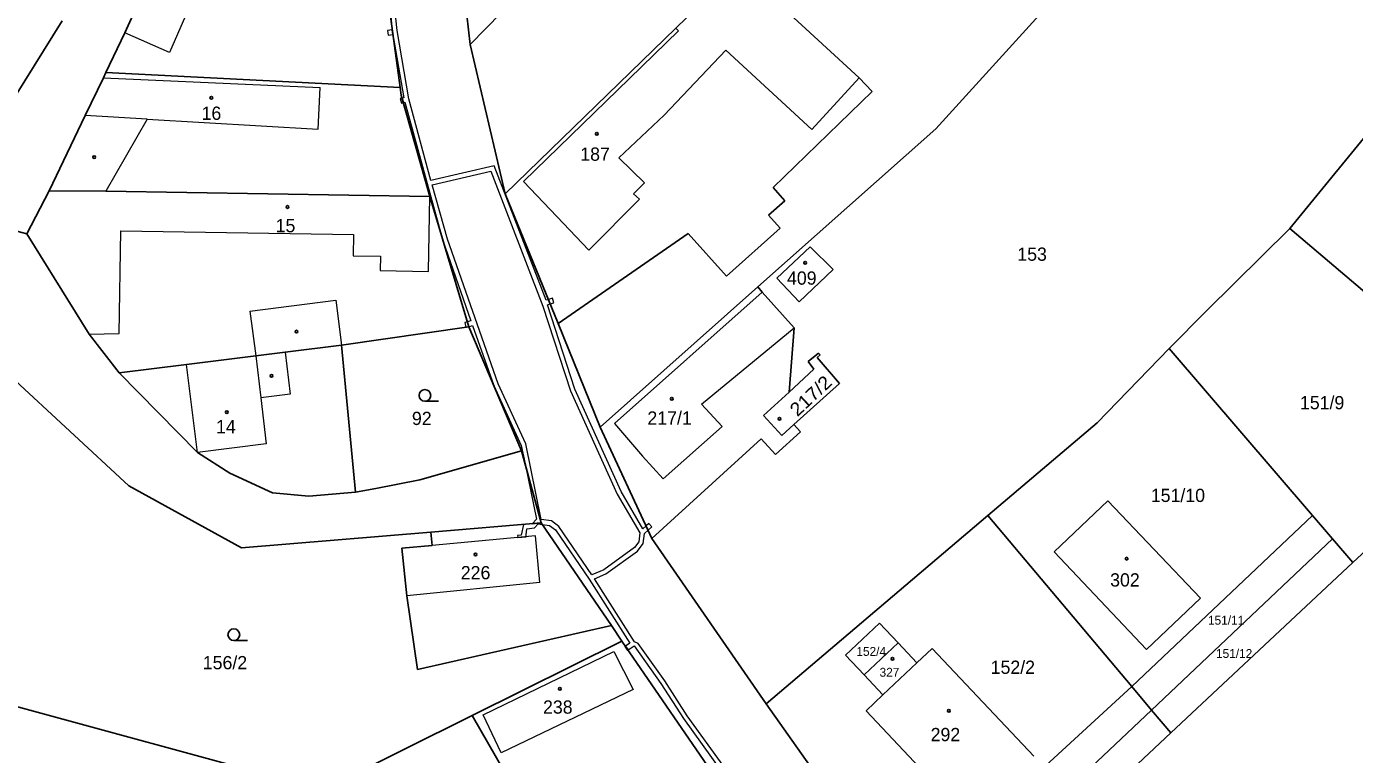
# Model space of a CAD drawing. Extents: x -694609 to -690140, y -1033292 to -1029794.
# Drawn here: x -693128 to -692957.6, y -1031416.8 to -1031323.3 of the extents above; entities that cross this region are included whole.
import ezdxf
from ezdxf.enums import TextEntityAlignment as Align

# ---------------------------------------------------------------- set-up
doc = ezdxf.new("R2010")
doc.units = 0
doc.header["$LTSCALE"] = 0.68
for name, color, linetype, lineweight in [('1', 7, 'Continuous', 25), ('13', 7, 'Continuous', 13), ('3', 7, 'Continuous', 25), ('4', 7, 'Continuous', 13), ('5', 7, 'Continuous', 25)]:
    doc.layers.add(name, color=color, linetype=linetype, lineweight=lineweight)
doc.layers.add('2', color=7, linetype='Continuous')

msp = doc.modelspace()

# ---------------------------------------------------------------- linework, layer by layer
at = {"layer": '1'}
for p, q in [((-693011.32, -1031336.45), (-692982.62, -1031304.77)), ((-693071.07, -1031325.64), (-693054.38, -1031308.42)), ((-693109.53, -1031311.17), (-693115.38, -1031324.14)), ((-693044.7, -1031323.52), (-693036.63, -1031315.66)), ((-693081.81, -1031318.46), (-693080.06, -1031331.16)), ((-693071.72, -1031320), (-693071.07, -1031325.64)), ((-693032.19, -1031319.75), (-693021.16, -1031329.91)), ((-693123.43, -1031322.59), (-693138.69, -1031347.09)), ((-693066.58, -1031344.79), (-693044.7, -1031323.52)), ((-693115.38, -1031324.14), (-693117.81, -1031329.22)), ((-693071.07, -1031325.64), (-693066.58, -1031344.79)), ((-693118.14, -1031329.9), (-693120.46, -1031334.74)), ((-693117.81, -1031329.22), (-693118.14, -1031329.9)), ((-693117.81, -1031329.22), (-693080.06, -1031331.16)), ((-693021.16, -1031329.91), (-693019.51, -1031331.67)), ((-693080.06, -1031331.16), (-693079.92, -1031332.14)), ((-693079.92, -1031332.14), (-693076.25, -1031345.16)), ((-693032.23, -1031344.01), (-693019.51, -1031331.67)), ((-693120.46, -1031334.74), (-693125.1, -1031344.42)), ((-692965.91, -1031349.24), (-692953.66, -1031334.24)), ((-693011.32, -1031336.45), (-693034.18, -1031356.76)), ((-693032.23, -1031344.01), (-693030.7, -1031345.69)), ((-693125.1, -1031344.42), (-693127.97, -1031349.93)), ((-693117.81, -1031344.47), (-693125.1, -1031344.42)), ((-693076.25, -1031345.16), (-693117.81, -1031344.47)), ((-693076.25, -1031345.16), (-693071.27, -1031361.86)), ((-693059.81, -1031361.44), (-693066.58, -1031344.79)), ((-693030.7, -1031345.69), (-693032.8, -1031347.55)), ((-693127.97, -1031349.93), (-693138.69, -1031347.09)), ((-693032.8, -1031347.55), (-693031.3, -1031349.23)), ((-693031.3, -1031349.23), (-693038.21, -1031355.38)), ((-692965.91, -1031349.24), (-692976.61, -1031359.82)), ((-692937.71, -1031373.28), (-692965.91, -1031349.24)), ((-693127.97, -1031349.93), (-693119.97, -1031362.82)), ((-693043.1, -1031349.89), (-693059.81, -1031361.44)), ((-693038.21, -1031355.38), (-693043.1, -1031349.89)), ((-693031.76, -1031355.61), (-693027.47, -1031351.59)), ((-693027.47, -1031351.59), (-693024.52, -1031354.53)), ((-693024.52, -1031354.53), (-693028.87, -1031358.66)), ((-693028.87, -1031358.66), (-693031.76, -1031355.61)), ((-693034.18, -1031356.76), (-693054.4, -1031374.74)), ((-693033.63, -1031357.42), (-693034.18, -1031356.76)), ((-693029.51, -1031362.02), (-693033.63, -1031357.42)), ((-692976.61, -1031359.82), (-692981.39, -1031364.66)), ((-693119.97, -1031362.82), (-693116.13, -1031367.79)), ((-693071.27, -1031361.86), (-693087.61, -1031364.21)), ((-693071.27, -1031361.86), (-693064.5, -1031377.79)), ((-693054.4, -1031374.74), (-693059.81, -1031361.44)), ((-693029.51, -1031362.02), (-693030.17, -1031370.26)), ((-693094.83, -1031365.12), (-693087.61, -1031364.21)), ((-693087.61, -1031364.21), (-693085.81, -1031383.1)), ((-692981.39, -1031364.66), (-692990.66, -1031374.2)), ((-692963.02, -1031386.08), (-692981.39, -1031364.66)), ((-693107.46, -1031366.7), (-693098.59, -1031365.59)), ((-693098.59, -1031365.59), (-693094.83, -1031365.12)), ((-693027.73, -1031366.32), (-693026.38, -1031365.25)), ((-693026.98, -1031367.32), (-693027.73, -1031366.32)), ((-693026.19, -1031365.47), (-693026.55, -1031365.8)), ((-693026.55, -1031365.8), (-693023.72, -1031369.16)), ((-693026.38, -1031365.25), (-693026.19, -1031365.47)), ((-693116.13, -1031367.79), (-693107.46, -1031366.7)), ((-693106.07, -1031377.99), (-693116.13, -1031367.79)), ((-693030.17, -1031370.26), (-693026.98, -1031367.32)), ((-693114.88, -1031382.29), (-693130.01, -1031368.23)), ((-693023.72, -1031369.16), (-693029.55, -1031374.43)), ((-693033.43, -1031373.27), (-693030.17, -1031370.26)), ((-693031.08, -1031375.81), (-693033.43, -1031373.27)), ((-692937.71, -1031373.28), (-692957.84, -1031392.12)), ((-693047.76, -1031389.03), (-693054.4, -1031374.74)), ((-693029.55, -1031374.43), (-693031.08, -1031375.81)), ((-693029.55, -1031374.43), (-693028.69, -1031375.34)), ((-692990.66, -1031374.2), (-693004.66, -1031386.09)), ((-693047.76, -1031389.03), (-693033.74, -1031376.23)), ((-693033.74, -1031376.23), (-693031.89, -1031378.26)), ((-693031.89, -1031378.26), (-693028.69, -1031375.34)), ((-693101.92, -1031380.67), (-693106.07, -1031377.99)), ((-693064.5, -1031377.79), (-693077.53, -1031381.5)), ((-693061.97, -1031387.05), (-693064.5, -1031377.79)), ((-693096.45, -1031383.16), (-693101.92, -1031380.67)), ((-693077.53, -1031381.5), (-693083.17, -1031382.62)), ((-693100.44, -1031390.24), (-693114.88, -1031382.29)), ((-693091.79, -1031383.6), (-693096.45, -1031383.16)), ((-693085.81, -1031383.1), (-693091.79, -1031383.6)), ((-693083.17, -1031382.62), (-693085.81, -1031383.1)), ((-692989.26, -1031384.2), (-692996.18, -1031390.76)), ((-692989.26, -1031384.2), (-692977.39, -1031396.72)), ((-693004.66, -1031386.09), (-693033.09, -1031410.25)), ((-692986.21, -1031408.04), (-693004.66, -1031386.09)), ((-692986.21, -1031408.04), (-692963.02, -1031386.08)), ((-692960.44, -1031389.09), (-692963.02, -1031386.08)), ((-693076.11, -1031388.22), (-693100.44, -1031390.24)), ((-693061.97, -1031387.05), (-693076.11, -1031388.22)), ((-693076.11, -1031388.22), (-693075.98, -1031389.94)), ((-693061.97, -1031387.05), (-693052.97, -1031400.22)), ((-693075.98, -1031389.94), (-693079.83, -1031390.3)), ((-693079.22, -1031396.38), (-693079.83, -1031390.3)), ((-693033.09, -1031410.25), (-693047.76, -1031389.03)), ((-692960.44, -1031389.09), (-692983.67, -1031411.06)), ((-692957.84, -1031392.12), (-692960.44, -1031389.09)), ((-692996.18, -1031390.76), (-692984.31, -1031403.28)), ((-692957.84, -1031392.12), (-692981.2, -1031414)), ((-693079.22, -1031396.38), (-693077.83, -1031405.87)), ((-692977.39, -1031396.72), (-692984.31, -1031403.28)), ((-693077.83, -1031405.87), (-693052.97, -1031400.22)), ((-693052.97, -1031400.22), (-693051.61, -1031402.21)), ((-693018.58, -1031399.89), (-693022.94, -1031404.01)), ((-693016.18, -1031402.43), (-693018.58, -1031399.89)), ((-693051.61, -1031402.21), (-693070.81, -1031411.75)), ((-693051.61, -1031402.21), (-693039.68, -1031419.57)), ((-693016.18, -1031402.43), (-693020.54, -1031406.55)), ((-693013.76, -1031405), (-693016.18, -1031402.43)), ((-693011.83, -1031403.18), (-693013.76, -1031405)), ((-693011.83, -1031403.18), (-692998.78, -1031416.98)), ((-693022.94, -1031404.01), (-693020.54, -1031406.55)), ((-693013.76, -1031405), (-693018.12, -1031409.12)), ((-693020.54, -1031406.55), (-693018.12, -1031409.12)), ((-693140.45, -1031407.6), (-693090.02, -1031421.29)), ((-693014.28, -1031433.8), (-692986.21, -1031408.04)), ((-692983.67, -1031411.06), (-692986.21, -1031408.04)), ((-693015.83, -1031434.75), (-693033.09, -1031410.25)), ((-693018.12, -1031409.12), (-693020.29, -1031411.17)), ((-693070.81, -1031411.75), (-693090.02, -1031421.29)), ((-693070.81, -1031411.75), (-693061.47, -1031427.99)), ((-693020.29, -1031411.17), (-693007.24, -1031424.98)), ((-692983.67, -1031411.06), (-693010.61, -1031436.53)), ((-692981.2, -1031414), (-692983.67, -1031411.06)), ((-692981.2, -1031414), (-693010.99, -1031441.88))]:
    msp.add_line(p, q, dxfattribs=at)
at = {"layer": '13'}
for points in [[(-693081.51, -1031319.46), (-693081.08, -1031323.75), (-693081, -1031324.34), (-693079.58, -1031332.47), (-693079.81, -1031332.52), (-693079.65, -1031333.09), (-693079.45, -1031333.05), (-693074.57, -1031350.8), (-693071, -1031361.1), (-693071.46, -1031361.23), (-693071.27, -1031361.86), (-693070.78, -1031361.72), (-693068.06, -1031369.42), (-693064.53, -1031377.09), (-693064.04, -1031379.46), (-693061.97, -1031387.05), (-693061.84, -1031387.24), (-693060.89, -1031387.36), (-693060.13, -1031387.91), (-693055.8, -1031394.27), (-693050.61, -1031402.48), (-693051.17, -1031402.85), (-693050.82, -1031403.35), (-693050.04, -1031402.82), (-693046.61, -1031407.65), (-693043.71, -1031412.16), (-693038.92, -1031418.81)], [(-693038.41, -1031418.49), (-693043.23, -1031411.8), (-693046.12, -1031407.31), (-693049.53, -1031402.51), (-693050, -1031402.32), (-693055.14, -1031394.21), (-693053.66, -1031393.59), (-693049.6, -1031390.66), (-693048.87, -1031389.69), (-693048.72, -1031388.4), (-693048.25, -1031387.98), (-693048.51, -1031387.41), (-693048.94, -1031387.79), (-693051.71, -1031383.03), (-693057.67, -1031369.88), (-693061.18, -1031359.05), (-693060.83, -1031358.94), (-693061.05, -1031358.38), (-693061.35, -1031358.47), (-693068.02, -1031341.19), (-693076.13, -1031343.08), (-693078.94, -1031332.62), (-693080.45, -1031323.83), (-693080.91, -1031319.43)]]:
    msp.add_lwpolyline(points, dxfattribs=at)
for points in [[(-693081.71, -1031323.85), (-693081.62, -1031324.44), (-693081, -1031324.34), (-693081.08, -1031323.75)], [(-693079.81, -1031332.52), (-693080.05, -1031332.58), (-693079.91, -1031333.15), (-693079.65, -1031333.09)], [(-693068.43, -1031341.91), (-693061.78, -1031359.2), (-693058.22, -1031370.1), (-693052.23, -1031383.33), (-693049.32, -1031388.31), (-693049.45, -1031389.46), (-693050.01, -1031390.21), (-693053.93, -1031393.05), (-693055.47, -1031393.7), (-693059.69, -1031387.49), (-693060.66, -1031386.78), (-693061.97, -1031386.62), (-693063.95, -1031376.91), (-693067.47, -1031369.18), (-693073.99, -1031350.62), (-693075.96, -1031343.66)], [(-693061.05, -1031358.38), (-693060.83, -1031358.94), (-693060.33, -1031358.78), (-693060.5, -1031358.21)], [(-693071.78, -1031361.33), (-693071.62, -1031361.91), (-693071.27, -1031361.86), (-693071.46, -1031361.23)], [(-693062.59, -1031386.55), (-693063.13, -1031387.15), (-693061.97, -1031387.05), (-693064.04, -1031379.46)], [(-693064.26, -1031387.24), (-693064.54, -1031388.62), (-693065, -1031388.66), (-693064.98, -1031388.92), (-693063.89, -1031388.82), (-693063.91, -1031388.56), (-693063.8, -1031387.82), (-693062.82, -1031387.69), (-693062.35, -1031387.17), (-693061.84, -1031387.24), (-693061.97, -1031387.05), (-693063.13, -1031387.15)], [(-693048.51, -1031387.41), (-693048.25, -1031387.98), (-693047.78, -1031387.56), (-693048.18, -1031387.11)], [(-693050.82, -1031403.35), (-693051.17, -1031402.85), (-693051.25, -1031402.91), (-693050.91, -1031403.41)]]:
    msp.add_lwpolyline(points, close=True, dxfattribs=at)
at = {"layer": '3'}
for p, q in [((-693076.893, -1031371.43), (-693075.143, -1031371.43)), ((-693101.403, -1031402.14), (-693099.653, -1031402.14))]:
    msp.add_line(p, q, dxfattribs=at)
for centre in [(-693076.8929, -1031370.6798), (-693101.4029, -1031401.3898)]:
    msp.add_circle(centre, 0.75, dxfattribs=at)
at = {"layer": '4'}
for p, q in [((-693105.91, -1031318.03), (-693109.66, -1031326.65)), ((-693050.64, -1031330), (-693044.35, -1031323.88)), ((-693044.35, -1031323.88), (-693044.7, -1031323.52)), ((-693109.66, -1031326.65), (-693115.38, -1031324.14)), ((-693046.2, -1031334.7), (-693038.29, -1031326.37)), ((-693038.29, -1031326.37), (-693027.26, -1031336.53)), ((-693118.14, -1031329.9), (-693090.33, -1031331.16)), ((-693064.24, -1031343.22), (-693050.64, -1031330)), ((-693027.26, -1031336.53), (-693021.16, -1031329.91)), ((-693090.58, -1031336.51), (-693090.33, -1031331.16)), ((-693112.54, -1031335.22), (-693120.46, -1031334.74)), ((-693112.54, -1031335.22), (-693117.81, -1031344.47)), ((-693112.54, -1031335.22), (-693090.58, -1031336.51)), ((-693046.2, -1031334.7), (-693052, -1031340.19)), ((-693048.71, -1031343.38), (-693052, -1031340.19)), ((-693064.24, -1031343.22), (-693059.97, -1031347.72)), ((-693050.13, -1031344.79), (-693048.71, -1031343.38)), ((-693076.41, -1031354.75), (-693076.25, -1031345.16)), ((-693055.88, -1031352.03), (-693049.38, -1031345.5)), ((-693049.38, -1031345.5), (-693050.13, -1031344.79)), ((-693059.97, -1031347.72), (-693055.88, -1031352.03)), ((-693116.11, -1031362.74), (-693115.89, -1031349.54)), ((-693115.89, -1031349.54), (-693086.04, -1031350.04)), ((-693086.04, -1031350.04), (-693086.09, -1031352.74)), ((-693086.09, -1031352.74), (-693082.59, -1031352.8)), ((-693082.59, -1031352.8), (-693082.62, -1031354.64)), ((-693082.62, -1031354.64), (-693076.41, -1031354.75)), ((-693033.63, -1031357.42), (-693052.58, -1031374.27)), ((-693099.33, -1031359.85), (-693088.33, -1031358.47)), ((-693088.33, -1031358.47), (-693087.61, -1031364.21)), ((-693099.33, -1031359.85), (-693098.59, -1031365.59)), ((-693119.97, -1031362.82), (-693116.11, -1031362.74)), ((-693041.42, -1031371.78), (-693029.51, -1031362.02)), ((-693098.59, -1031365.59), (-693097.95, -1031371)), ((-693094.83, -1031365.12), (-693094.16, -1031370.53)), ((-693106.07, -1031377.99), (-693107.46, -1031366.7)), ((-693094.16, -1031370.53), (-693097.95, -1031371)), ((-693038.77, -1031374.67), (-693041.42, -1031371.78)), ((-693052.58, -1031374.27), (-693048.96, -1031378.48)), ((-693046.31, -1031381.37), (-693038.77, -1031374.67)), ((-693048.96, -1031378.48), (-693046.31, -1031381.37)), ((-693062.7, -1031388.71), (-693075.98, -1031389.94)), ((-693062.15, -1031394.67), (-693062.7, -1031388.71)), ((-693062.15, -1031394.67), (-693079.22, -1031396.38)), ((-693069.41, -1031411.68), (-693052.65, -1031403.53)), ((-693052.65, -1031403.53), (-693050.17, -1031408.42)), ((-693050.17, -1031408.42), (-693067.1, -1031416.54)), ((-693067.1, -1031416.54), (-693069.41, -1031411.68))]:
    msp.add_line(p, q, dxfattribs=at)
msp.add_lwpolyline([(-693097.95, -1031371), (-693097.26, -1031376.9), (-693106.07, -1031377.99)], dxfattribs=at)
at = {"layer": '5'}
for centre in [(-693104.2868, -1031332.4792), (-693054.8468, -1031337.0892), (-693119.3068, -1031340.0792), (-693094.5068, -1031346.4892), (-693028.1068, -1031353.6592), (-693093.3768, -1031362.4892), (-693096.5668, -1031368.1792), (-693045.2268, -1031371.1092), (-693102.3168, -1031372.8192), (-693031.3968, -1031373.6792), (-693070.3968, -1031391.0792), (-692986.8568, -1031391.6292), (-693016.9068, -1031404.4892), (-693059.5668, -1031408.3392), (-693009.6668, -1031411.1492)]:
    msp.add_circle(centre, 0.175, dxfattribs=at)

# ---------------------------------------------------------------- texts
at = {"layer": '2'}
for s, height, p in [('16', 1.7, (-693104.279, -1031335.305)), ('187', 1.7, (-693055.059, -1031340.555)), ('15', 1.7, (-693094.779, -1031349.735)), ('153', 1.7, (-692998.989, -1031353.395)), ('409', 1.7, (-693028.539, -1031356.465)), ('151/9', 1.7, (-692961.78, -1031372.455)), ('92', 1.7, (-693077.289, -1031374.475)), ('217/1', 1.7, (-693045.5, -1031374.425)), ('14', 1.7, (-693102.419, -1031375.535)), ('151/10', 1.7, (-692980.28, -1031384.355)), ('226', 1.7, (-693070.389, -1031394.275)), ('302', 1.7, (-692987.079, -1031395.205)), ('151/11', 1.14, (-692974.099, -1031400.105)), ('152/4', 1.14, (-693019.629, -1031404.105)), ('151/12', 1.14, (-692973.069, -1031404.375)), ('156/2', 1.7, (-693102.54, -1031405.825)), ('327', 1.14, (-693017.29, -1031406.785)), ('152/2', 1.7, (-693001.46, -1031406.415)), ('238', 1.7, (-693059.839, -1031411.525)), ('292', 1.7, (-693010.109, -1031415.055))]:
    msp.add_text(s, height=height, dxfattribs=at).set_placement(p, align=Align.CENTER)
at = {"layer": '2', "width": 1.1}
msp.add_text('217/2', height=1.7, rotation=43, dxfattribs=at).set_placement((-693026.8147, -1031371.3456), align=Align.CENTER)

doc.saveas('drawing.dxf')
